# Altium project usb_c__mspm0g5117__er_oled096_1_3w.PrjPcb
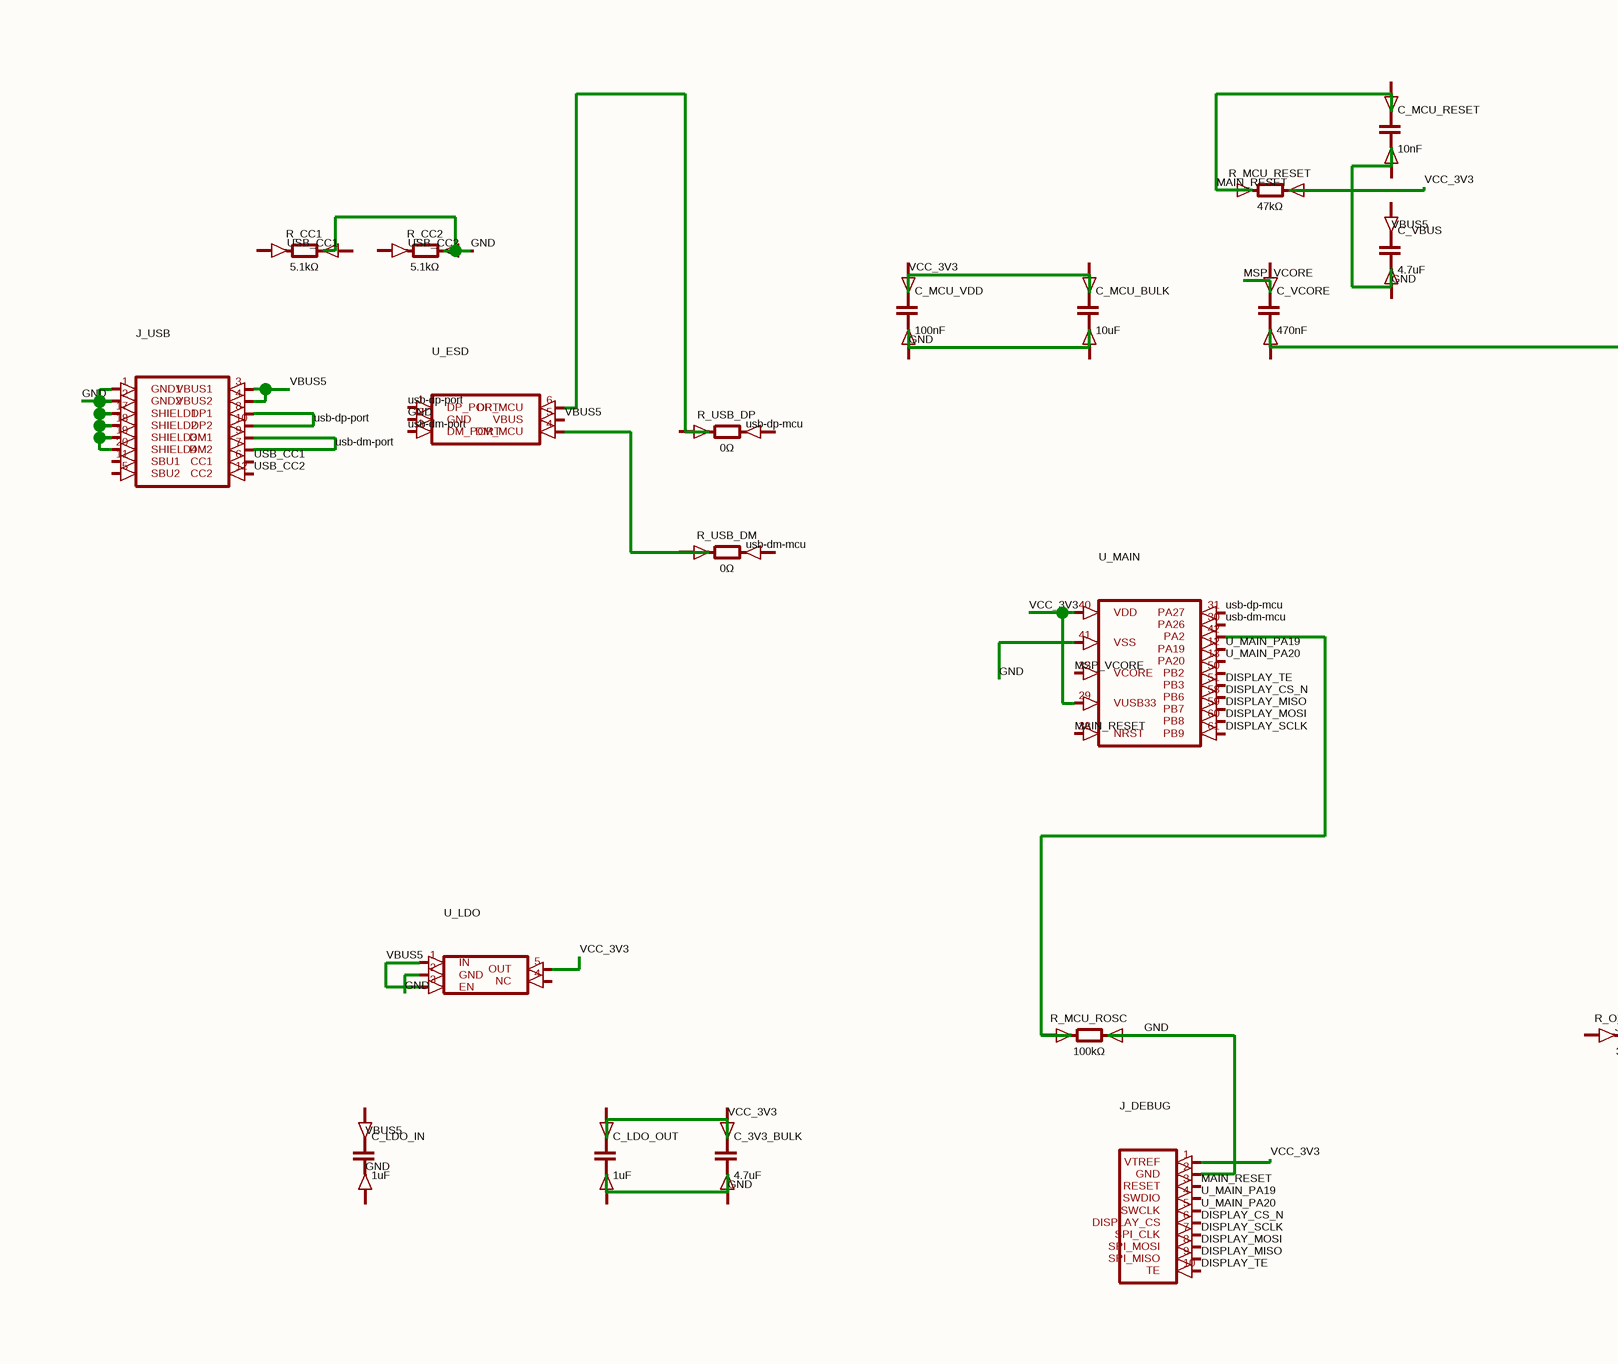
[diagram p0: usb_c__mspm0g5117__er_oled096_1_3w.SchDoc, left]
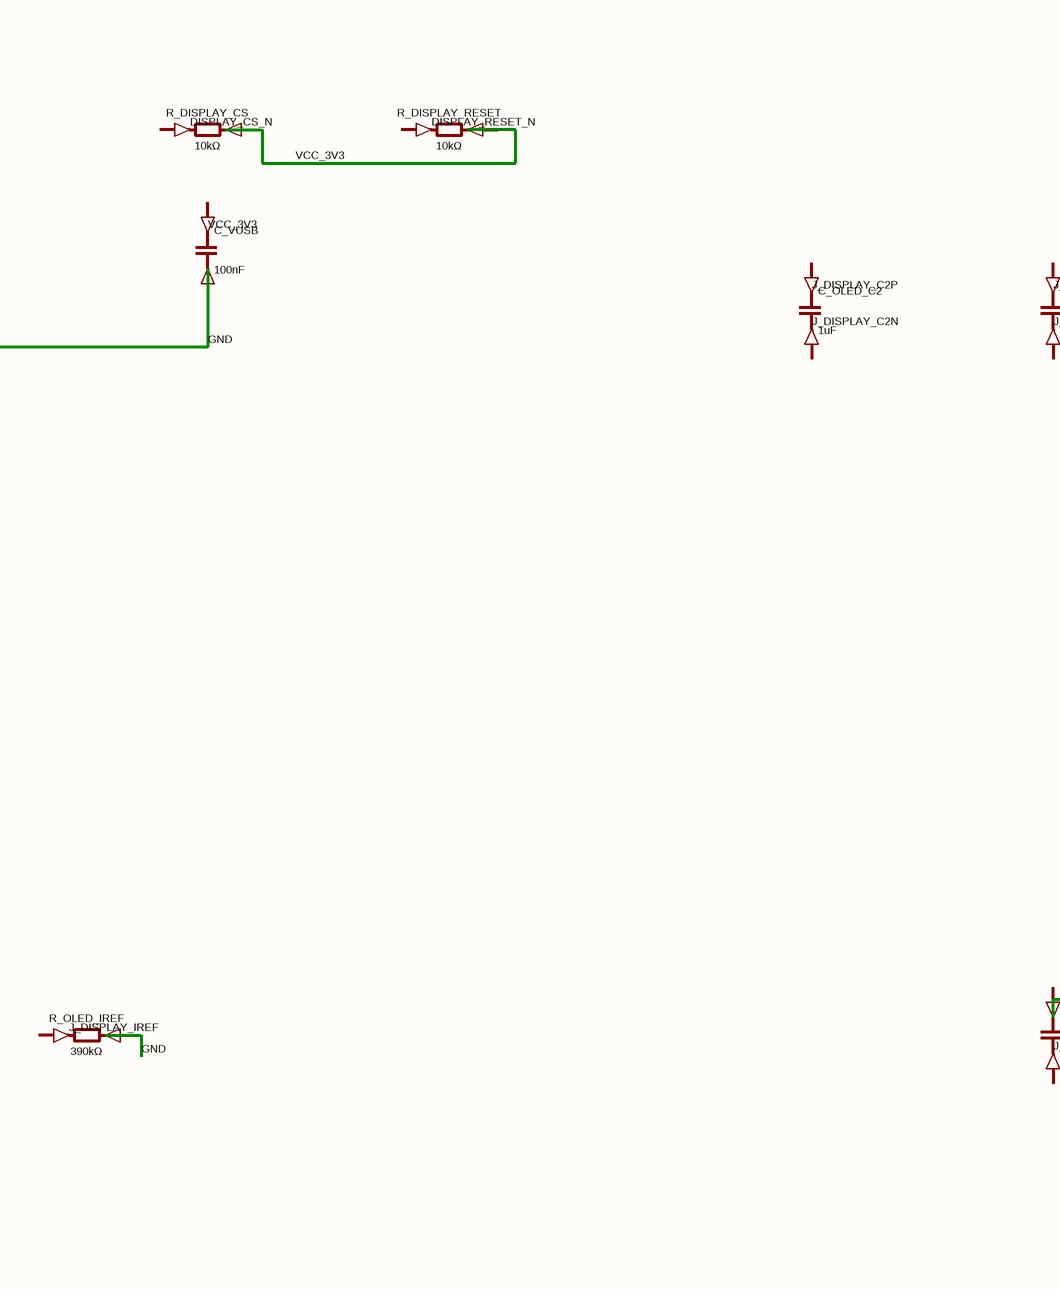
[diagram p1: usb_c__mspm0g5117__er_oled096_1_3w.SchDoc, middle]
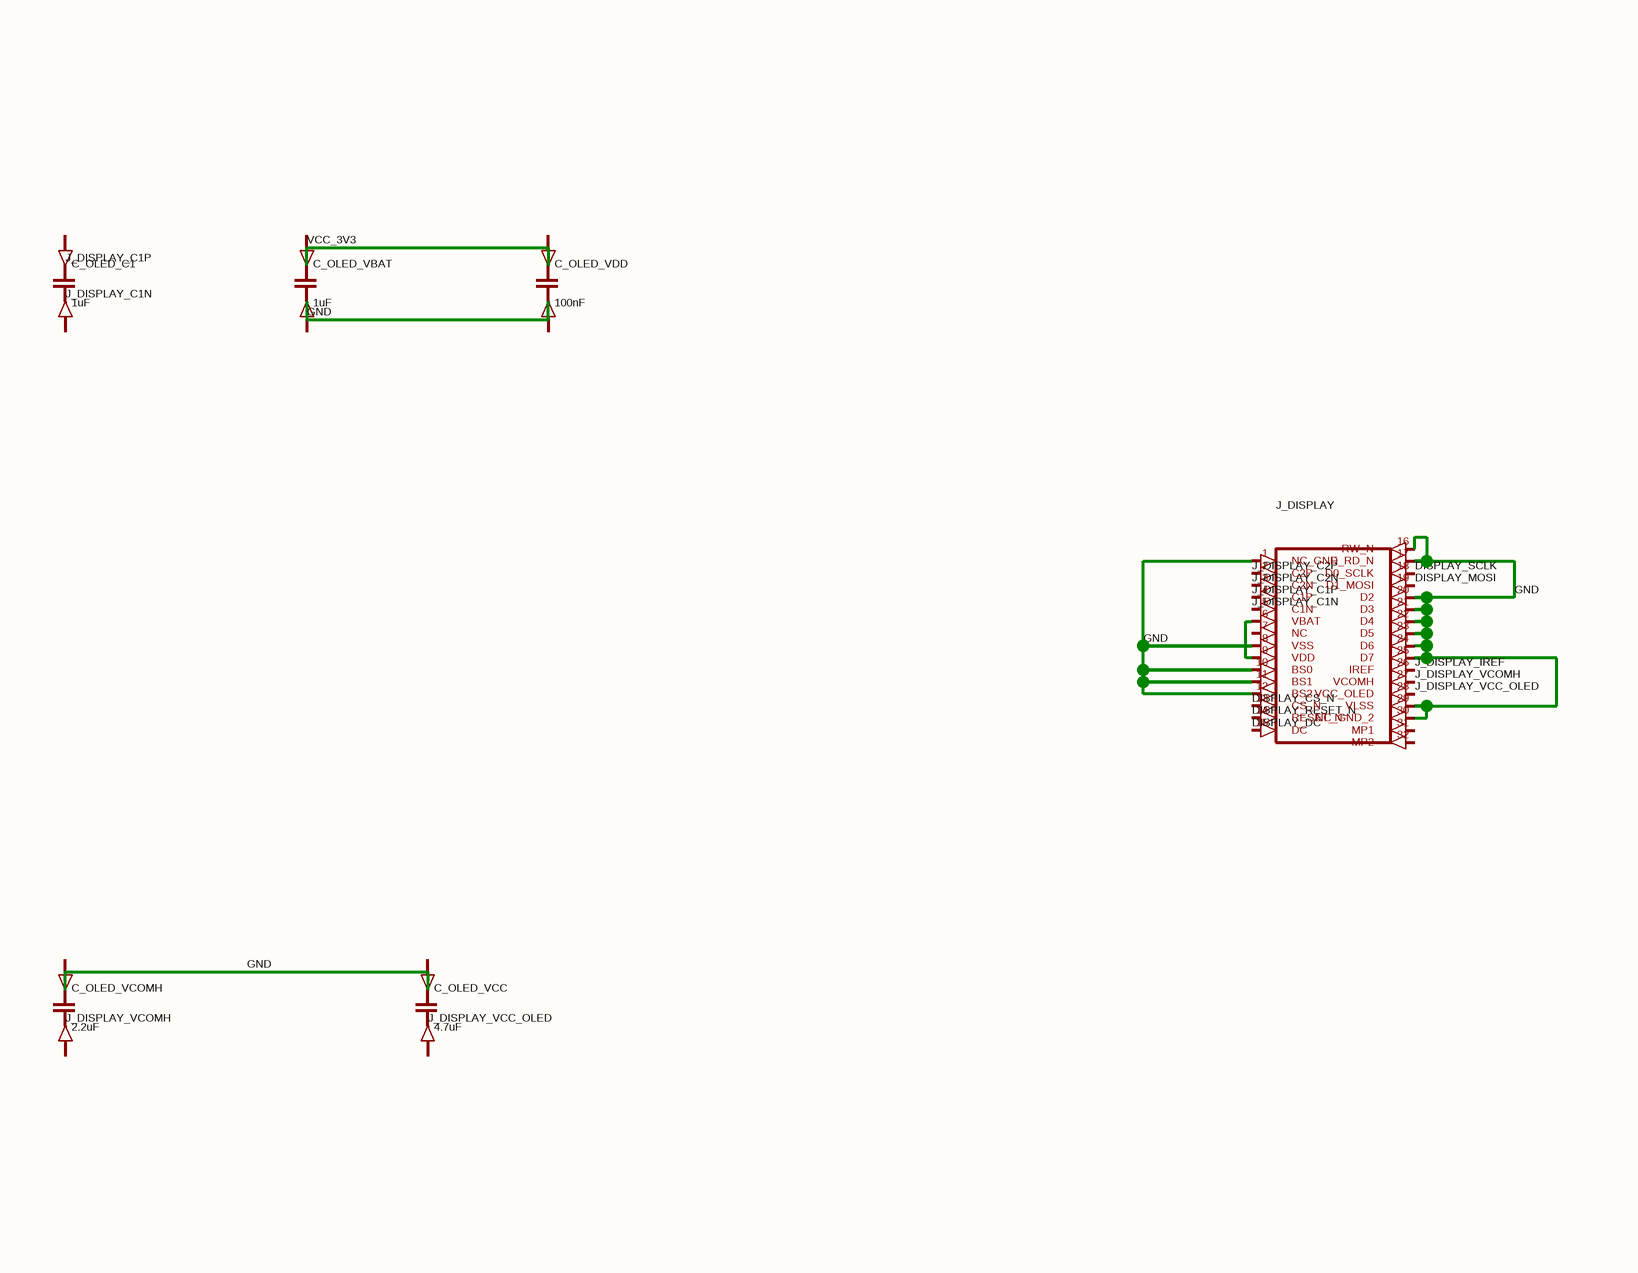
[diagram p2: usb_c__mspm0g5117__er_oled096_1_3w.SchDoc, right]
1 sheet, 30 parts. Net scope: global (net labels, ports and power ports of the same name join across sheets).
Board file: usb_c__mspm0g5117__er_oled096_1_3w.PcbDoc

## Sheet usb_c__mspm0g5117__er_oled096_1_3w.SchDoc
size 388 x 149 mm

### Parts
C_3V3_BULK  4.7uF
C_LDO_IN  1uF
C_LDO_OUT  1uF
C_MCU_BULK  10uF
C_MCU_RESET  10nF
C_MCU_VDD  100nF
C_OLED_C1  1uF
C_OLED_C2  1uF
C_OLED_VBAT  1uF
C_OLED_VCC  4.7uF
C_OLED_VCOMH  2.2uF
C_OLED_VDD  100nF
C_VBUS  4.7uF
C_VCORE  470nF
C_VUSB  100nF
J_DEBUG  (no value)
J_DISPLAY  (no value)
J_USB  (no value)
R_CC1  5.1kΩ
R_CC2  5.1kΩ
R_DISPLAY_CS  10kΩ
R_DISPLAY_RESET  10kΩ
R_MCU_RESET  47kΩ
R_MCU_ROSC  100kΩ
R_OLED_IREF  390kΩ
R_USB_DM  0Ω
R_USB_DP  0Ω
U_ESD  (no value)
U_LDO  (no value)
U_MAIN  (no value)

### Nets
DISPLAY_CS_N: J_DEBUG.6(DISPLAY_CS) J_DISPLAY.13(CS_N) U_MAIN.58(PB6)
DISPLAY_DC: J_DISPLAY.15(DC)
DISPLAY_MISO: J_DEBUG.9(SPI_MISO) U_MAIN.59(PB7)
DISPLAY_MOSI: J_DEBUG.8(SPI_MOSI) J_DISPLAY.19(D1_MOSI) U_MAIN.60(PB8)
DISPLAY_RESET_N: J_DISPLAY.14(RESET_N)
DISPLAY_SCLK: J_DEBUG.7(SPI_CLK) J_DISPLAY.18(D0_SCLK) U_MAIN.61(PB9)
DISPLAY_TE: J_DEBUG.10(TE) U_MAIN.51(PB3)
GND: C_VUSB.2(cathode) J_DEBUG.1(VTREF) J_DEBUG.2(GND) J_DISPLAY.1(NC_GND) J_DISPLAY.6(VBAT) J_DISPLAY.8(VSS) J_DISPLAY.9(VDD) J_DISPLAY.10(BS0) J_DISPLAY.11(BS1) J_DISPLAY.12(BS2) J_DISPLAY.16(RW_N) J_DISPLAY.17(E_RD_N) J_DISPLAY.20(D2) J_DISPLAY.21(D3) J_DISPLAY.22(D4) J_DISPLAY.23(D5) J_DISPLAY.24(D6) J_DISPLAY.25(D7) J_DISPLAY.29(VLSS) J_DISPLAY.30(NC_GND_2) J_USB.1(GND1) J_USB.2(GND2) J_USB.3(VBUS1) J_USB.4(VBUS2) J_USB.17(SHIELD1) J_USB.18(SHIELD2) J_USB.19(SHIELD3) J_USB.20(SHIELD4) R_DISPLAY_CS.2(cathode) R_DISPLAY_RESET.2(cathode) R_MCU_RESET.2(cathode) R_MCU_ROSC.2(cathode) R_OLED_IREF.2(cathode) U_ESD.2(GND) U_ESD.5(VBUS) U_LDO.1(IN) U_LDO.2(GND) U_LDO.3(EN) U_LDO.5(OUT) U_MAIN.29(VUSB33) U_MAIN.40(VDD) U_MAIN.41(VSS)  [also labelled VBUS5, VCC_3V3]
J_DISPLAY_C1N: J_DISPLAY.5(C1N)
J_DISPLAY_C1P: J_DISPLAY.4(C1P)
J_DISPLAY_C2N: J_DISPLAY.3(C2N)
J_DISPLAY_C2P: J_DISPLAY.2(C2P)
J_DISPLAY_IREF: J_DISPLAY.26(IREF)
J_DISPLAY_VCC_OLED: J_DISPLAY.28(VCC_OLED)
J_DISPLAY_VCOMH: J_DISPLAY.27(VCOMH)
MAIN_RESET: J_DEBUG.3(RESET) R_MCU_RESET.1(anode) U_MAIN.38(NRST)
MSP_VCORE: U_MAIN.32(VCORE)
U_MAIN_PA19: J_DEBUG.4(SWDIO) U_MAIN.12(PA19)
U_MAIN_PA20: J_DEBUG.5(SWCLK) U_MAIN.13(PA20)
usb-dm-mcu: U_MAIN.30(PA26)
usb-dm-port: J_USB.7(DM2) J_USB.9(DM1) U_ESD.3(DM_PORT)
usb-dp-mcu: U_MAIN.31(PA27)
usb-dp-port: J_USB.8(DP1) J_USB.10(DP2) U_ESD.1(DP_PORT)
USB_CC1: J_USB.6(CC1)
USB_CC2: J_USB.12(CC2)
NetR_MCU_ROSC_1: R_MCU_ROSC.1(anode) U_MAIN.42(PA2)
NetR_USB_DM_1: R_USB_DM.1(anode) U_ESD.4(DM_MCU)

Not connected (* = marked no-connect by the designer): C_3V3_BULK 1(anode) 2(cathode); C_LDO_IN 1(anode) 2(cathode); C_LDO_OUT 1(anode) 2(cathode); C_MCU_BULK 1(anode) 2(cathode); C_MCU_RESET 1(anode) 2(cathode); C_MCU_VDD 1(anode) 2(cathode); C_OLED_C1 1(anode) 2(cathode); C_OLED_C2 1(anode) 2(cathode); C_OLED_VBAT 1(anode) 2(cathode); C_OLED_VCC 1(anode) 2(cathode); C_OLED_VCOMH 1(anode) 2(cathode); C_OLED_VDD 1(anode) 2(cathode); C_VBUS 1(anode) 2(cathode); C_VCORE 1(anode) 2(cathode); C_VUSB 1(anode); J_DISPLAY 7(NC) 31(MP1) 32(MP2); J_USB 5(SBU2) 11(SBU1); R_CC1 1(anode) 2(cathode); R_CC2 1(anode) 2(cathode); R_DISPLAY_CS 1(anode); R_DISPLAY_RESET 1(anode); R_OLED_IREF 1(anode); R_USB_DM 2(cathode); R_USB_DP 1(anode) 2(cathode); U_ESD 6(DP_MCU); U_LDO 4(NC); U_MAIN 50(PB2)

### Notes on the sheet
- Labels drawn without touching a wire or pin: DISPLAY_CS_N, DISPLAY_RESET_N, GND, J_DISPLAY_C1N, J_DISPLAY_C1P, J_DISPLAY_C2N, J_DISPLAY_C2P, J_DISPLAY_IREF, J_DISPLAY_VCC_OLED, J_DISPLAY_VCOMH, usb-dm-mcu, usb-dp-mcu, USB_CC1, USB_CC2, VBUS5, VCC_3V3

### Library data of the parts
C_3V3_BULK C_LDO_IN C_LDO_OUT C_MCU_BULK C_MCU_RESET C_MCU_VDD C_OLED_C1 C_OLED_C2 C_OLED_VBAT C_OLED_VCC C_OLED_VCOMH C_OLED_VDD C_VBUS C_VCORE C_VUSB = capacitor_down
J_DEBUG = J_DEBUG
J_DISPLAY = J_DISPLAY
J_USB = J_USB
R_CC1 R_CC2 R_DISPLAY_CS R_DISPLAY_RESET R_MCU_RESET R_MCU_ROSC R_OLED_IREF R_USB_DM R_USB_DP = boxresistor_right
U_ESD = U_ESD
U_LDO = U_LDO
U_MAIN = U_MAIN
